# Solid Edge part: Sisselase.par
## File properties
Author: Türk
Template: iso part.par
Last saved by: Türk
Revision: 14
Application: Solid Edge
Accuracy: 0,990
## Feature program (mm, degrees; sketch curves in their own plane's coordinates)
thread "unnamed Thread 1"
thread "unnamed Thread 2"
thread "unnamed Thread 3"
thread "unnamed Thread 4"
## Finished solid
Body 1: solid body, 316 faces, 807 edges, 476 vertices.
  Faces by surface: cylinder 109, blend 90, plane 88, torus 29
  Edges by curve: line 384, circle 274, intersection 138, ellipse 11
Bounding box of the edges (mm; curved faces can reach further): 628.000 x 249.108 x 180.552, from (-305, -244.1082, -163.0516) to (323, 5, 17.5).
Cylindrical faces by radius (mm): R1.1 x9, R4.594 x1, R4.7295 x3, R5 x1, R5.9952 x20, R15 x10, R20 x36, R42.5 x1, R47.5 x1, R50 x1, R55 x3, R60 x3, R143 x5, R145 x5, R175 x5, R177 x5
Toroidal faces (ring radius, tube radius in mm): R35 r20 x3, R40 r20 x6, R160 r15 x10, R160 r17 x10
Planar faces by outward normal: +x 13, +y 3, +z 14, -x 11, -y 9, -z 14, oblique 24
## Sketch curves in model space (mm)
line (300, -111.437, -6.0818) -> (300, -77.0224, -55.231)
line (0, 0, -160) -> (138.9702, 0, -160)
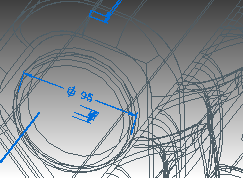
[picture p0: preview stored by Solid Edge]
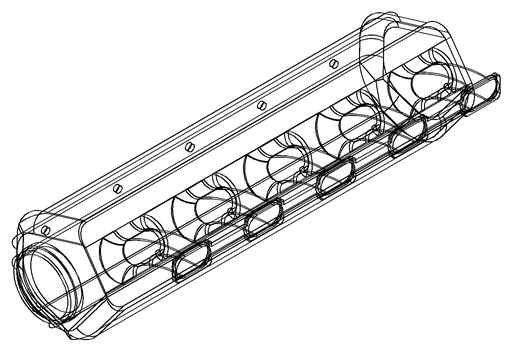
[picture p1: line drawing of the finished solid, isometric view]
